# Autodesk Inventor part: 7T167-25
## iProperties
Created: 2008-02
Part Number: 7T167-25
Document SubType Name: Modeling
Designer: Darius
Author: Darius
Translation Standard: STEP AP203
File Name: 7T167-25.STEP
Preprocessor: SolidWorks 2003240
Postprocessor: Build: 270, Release: 10 SP2 - Date: Mon 09/26/2005
Sent Units: MILLIMETERS
Uncertainty: 1e-05
